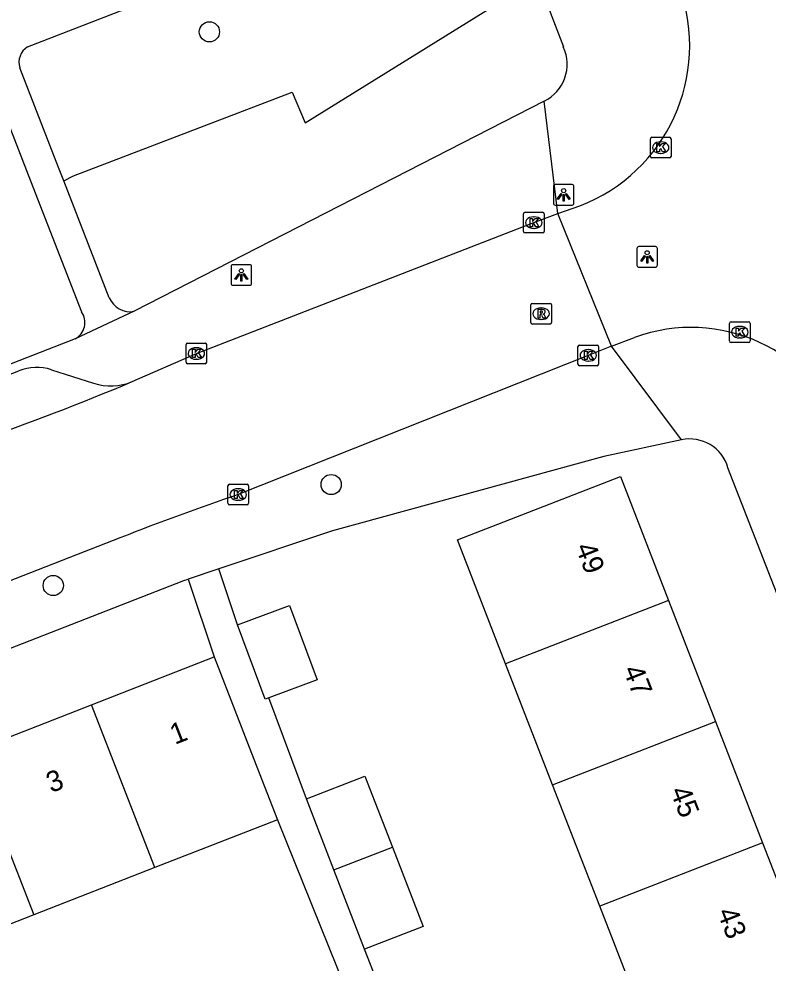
# Model space of a CAD drawing. Extents: x 159689 to 160786, y 387323 to 388339.
# Drawn here: x 160185.07 to 160221.36, y 387694.59 to 387740.35 of the extents above; entities that cross this region are included whole.
import ezdxf

# ---------------------------------------------------------------- set-up
doc = ezdxf.new("R2010")
doc.units = 0
for name, color, linetype in [('IMGEO_Boom', 7, 'Continuous'), ('IMGEO_Groenvoorziening', 7, 'Continuous'), ('IMGEO_Kolk', 7, 'Continuous'), ('IMGEO_Lichtpunt', 7, 'Continuous'), ('IMGEO_Pand', 7, 'Continuous'), ('IMGEO_Pand_nummerreeks', 7, 'Continuous'), ('IMGEO_Rijbaan_lokaal_gesloten', 7, 'Continuous'), ('IMGEO_Rijbaan_lokaal_open', 7, 'Continuous'), ('IMGEO_Rioolput', 7, 'Continuous'), ('IMGEO_Voetpad_open', 7, 'Continuous')]:
    doc.layers.add(name, color=color, linetype=linetype)

msp = doc.modelspace()

# ---------------------------------------------------------------- linework, layer by layer
at = {"layer": 'IMGEO_Boom'}
for centre in [(160194.295, 387739.718), (160200.196, 387717.781), (160186.733, 387712.89)]:
    msp.add_circle(centre, 0.489, dxfattribs=at)
at = {"layer": 'IMGEO_Groenvoorziening'}
msp.add_lwpolyline([(160187.24, 387732.505), (160187.714, 387732.742), (160198.307, 387736.801), (160198.939, 387735.303), (160208.031, 387740.94), (160210.196, 387742.282)], dxfattribs=at)
at = {"layer": 'IMGEO_Kolk'}
for p, q in [((160215.658, 387733.681), (160215.658, 387734.533)), ((160215.733, 387734.607), (160216.585, 387734.607)), ((160216.146, 387734.387), (160216.171, 387734.387)), ((160216.659, 387734.533), (160216.659, 387733.681)), ((160216.585, 387733.607), (160215.733, 387733.607)), ((160216.169, 387733.827), (160216.144, 387733.827)), ((160209.511, 387730.049), (160209.511, 387730.901)), ((160209.586, 387730.975), (160210.438, 387730.975)), ((160209.999, 387730.755), (160210.024, 387730.755)), ((160210.512, 387730.901), (160210.512, 387730.049)), ((160210.438, 387729.975), (160209.586, 387729.975)), ((160210.022, 387730.195), (160209.997, 387730.195)), ((160219.491, 387724.741), (160219.491, 387725.593)), ((160219.566, 387725.667), (160220.418, 387725.667)), ((160219.979, 387725.447), (160220.004, 387725.447)), ((160220.492, 387725.593), (160220.492, 387724.741)), ((160220.002, 387724.887), (160219.977, 387724.887)), ((160193.162, 387723.708), (160193.162, 387724.56)), ((160193.237, 387724.634), (160194.089, 387724.634)), ((160193.65, 387724.414), (160193.675, 387724.414)), ((160194.163, 387724.56), (160194.163, 387723.708)), ((160212.151, 387723.616), (160212.151, 387724.468)), ((160212.226, 387724.542), (160213.078, 387724.542)), ((160212.639, 387724.322), (160212.664, 387724.322)), ((160213.152, 387724.468), (160213.152, 387723.616)), ((160220.418, 387724.667), (160219.566, 387724.667)), ((160193.673, 387723.854), (160193.648, 387723.854)), ((160194.089, 387723.634), (160193.237, 387723.634)), ((160213.078, 387723.542), (160212.226, 387723.542)), ((160212.662, 387723.762), (160212.637, 387723.762)), ((160195.193, 387716.872), (160195.193, 387717.724)), ((160195.268, 387717.798), (160196.12, 387717.798)), ((160195.681, 387717.578), (160195.706, 387717.578)), ((160196.194, 387717.724), (160196.194, 387716.872)), ((160195.704, 387717.018), (160195.679, 387717.018)), ((160196.12, 387716.798), (160195.268, 387716.798))]:
    msp.add_line(p, q, dxfattribs=at)
for points in [[(160215.658, 387733.681), (160215.658, 387734.533)], [(160215.733, 387734.607), (160216.585, 387734.607)], [(160216.659, 387734.533), (160216.659, 387733.681)], [(160215.979, 387734.307), (160216.102, 387734.307), (160216.102, 387734.156), (160216.232, 387734.307), (160216.396, 387734.307), (160216.25, 387734.156), (160216.403, 387733.907), (160216.251, 387733.907), (160216.166, 387734.071), (160216.102, 387734.004), (160216.102, 387733.907), (160215.979, 387733.907), (160215.979, 387734.307)], [(160216.585, 387733.607), (160215.733, 387733.607)], [(160209.511, 387730.049), (160209.511, 387730.901)], [(160209.586, 387730.975), (160210.438, 387730.975)], [(160210.512, 387730.901), (160210.512, 387730.049)], [(160209.832, 387730.675), (160209.955, 387730.675), (160209.955, 387730.524), (160210.085, 387730.675), (160210.249, 387730.675), (160210.103, 387730.524), (160210.256, 387730.275), (160210.104, 387730.275), (160210.019, 387730.439), (160209.955, 387730.372), (160209.955, 387730.275), (160209.832, 387730.275), (160209.832, 387730.675)], [(160210.438, 387729.975), (160209.586, 387729.975)], [(160219.491, 387724.741), (160219.491, 387725.593)], [(160219.566, 387725.667), (160220.418, 387725.667)], [(160219.812, 387725.367), (160219.935, 387725.367), (160219.935, 387725.216), (160220.065, 387725.367), (160220.229, 387725.367), (160220.083, 387725.216), (160220.236, 387724.967), (160220.084, 387724.967), (160219.999, 387725.131), (160219.935, 387725.064), (160219.935, 387724.967), (160219.812, 387724.967), (160219.812, 387725.367)], [(160220.492, 387725.593), (160220.492, 387724.741)], [(160193.162, 387723.708), (160193.162, 387724.56)], [(160193.237, 387724.634), (160194.089, 387724.634)], [(160193.483, 387724.334), (160193.606, 387724.334), (160193.606, 387724.183), (160193.736, 387724.334), (160193.9, 387724.334), (160193.754, 387724.183), (160193.907, 387723.934), (160193.755, 387723.934), (160193.67, 387724.098), (160193.606, 387724.031), (160193.606, 387723.934), (160193.483, 387723.934), (160193.483, 387724.334)], [(160194.163, 387724.56), (160194.163, 387723.708)], [(160212.151, 387723.616), (160212.151, 387724.468)], [(160212.226, 387724.542), (160213.078, 387724.542)], [(160213.152, 387724.468), (160213.152, 387723.616)], [(160220.418, 387724.667), (160219.566, 387724.667)], [(160212.472, 387724.242), (160212.595, 387724.242), (160212.595, 387724.091), (160212.725, 387724.242), (160212.889, 387724.242), (160212.743, 387724.091), (160212.896, 387723.842), (160212.744, 387723.842), (160212.659, 387724.006), (160212.595, 387723.939), (160212.595, 387723.842), (160212.472, 387723.842), (160212.472, 387724.242)], [(160194.089, 387723.634), (160193.237, 387723.634)], [(160213.078, 387723.542), (160212.226, 387723.542)], [(160195.193, 387716.872), (160195.193, 387717.724)], [(160195.268, 387717.798), (160196.12, 387717.798)], [(160195.514, 387717.498), (160195.637, 387717.498), (160195.637, 387717.347), (160195.767, 387717.498), (160195.931, 387717.498), (160195.785, 387717.347), (160195.938, 387717.098), (160195.786, 387717.098), (160195.701, 387717.262), (160195.637, 387717.195), (160195.637, 387717.098), (160195.514, 387717.098), (160195.514, 387717.498)], [(160196.194, 387717.724), (160196.194, 387716.872)], [(160196.12, 387716.798), (160195.268, 387716.798)]]:
    msp.add_lwpolyline(points, dxfattribs=at)
for centre, start, end in [((160215.735, 387734.531), 91.552, 178.448), ((160215.735, 387734.531), 91.552, 178.448), ((160216.583, 387734.531), 1.552, 88.448), ((160216.583, 387734.531), 1.552, 88.448), ((160215.735, 387733.683), 181.552, 268.448), ((160215.735, 387733.683), 181.552, 268.448), ((160216.583, 387733.683), 271.552, 358.448), ((160216.583, 387733.683), 271.552, 358.448), ((160209.588, 387730.899), 91.552, 178.448), ((160209.588, 387730.899), 91.552, 178.448), ((160210.436, 387730.899), 1.552, 88.448), ((160210.436, 387730.899), 1.552, 88.448), ((160209.588, 387730.051), 181.552, 268.448), ((160209.588, 387730.051), 181.552, 268.448), ((160210.436, 387730.051), 271.552, 358.448), ((160210.436, 387730.051), 271.552, 358.448), ((160219.568, 387725.591), 91.552, 178.448), ((160219.568, 387725.591), 91.552, 178.448), ((160220.416, 387725.591), 1.552, 88.448), ((160220.416, 387725.591), 1.552, 88.448), ((160193.239, 387724.558), 91.552, 178.448), ((160193.239, 387724.558), 91.552, 178.448), ((160194.087, 387724.558), 1.552, 88.448), ((160194.087, 387724.558), 1.552, 88.448), ((160212.228, 387724.466), 91.552, 178.448), ((160212.228, 387724.466), 91.552, 178.448), ((160213.076, 387724.466), 1.552, 88.448), ((160213.076, 387724.466), 1.552, 88.448), ((160219.568, 387724.743), 181.552, 268.448), ((160219.568, 387724.743), 181.552, 268.448), ((160220.416, 387724.743), 271.552, 358.448), ((160220.416, 387724.743), 271.552, 358.448), ((160193.239, 387723.71), 181.552, 268.448), ((160193.239, 387723.71), 181.552, 268.448), ((160194.087, 387723.71), 271.552, 358.448), ((160194.087, 387723.71), 271.552, 358.448), ((160212.228, 387723.618), 181.552, 268.448), ((160212.228, 387723.618), 181.552, 268.448), ((160213.076, 387723.618), 271.552, 358.448), ((160213.076, 387723.618), 271.552, 358.448), ((160195.27, 387717.722), 91.552, 178.448), ((160195.27, 387717.722), 91.552, 178.448), ((160196.118, 387717.722), 1.552, 88.448), ((160196.118, 387717.722), 1.552, 88.448), ((160195.27, 387716.874), 181.552, 268.448), ((160195.27, 387716.874), 181.552, 268.448), ((160196.118, 387716.874), 271.552, 358.448), ((160196.118, 387716.874), 271.552, 358.448)]:
    msp.add_arc(centre, 0.0765, start, end, dxfattribs=at)
for centre, major_axis, ratio, start_param, end_param in [((160216.145, 387734.107), (-0.387, 0.002), 0.722429, 4.712389, 7.853982), ((160216.17, 387734.107), (-0.39, 0.002), 0.717154, 1.570796, 4.712389), ((160209.998, 387730.475), (-0.387, 0.002), 0.722429, 4.712389, 7.853982), ((160210.023, 387730.475), (-0.39, 0.002), 0.717154, 1.570796, 4.712389), ((160219.978, 387725.167), (-0.387, 0.002), 0.722429, 4.712389, 7.853982), ((160220.003, 387725.167), (-0.39, 0.002), 0.717154, 1.570796, 4.712389), ((160193.649, 387724.134), (-0.387, 0.002), 0.722429, 4.712389, 7.853982), ((160193.674, 387724.134), (-0.39, 0.002), 0.717154, 1.570796, 4.712389), ((160212.638, 387724.042), (-0.387, 0.002), 0.722429, 4.712389, 7.853982), ((160212.663, 387724.042), (-0.39, 0.002), 0.717154, 1.570796, 4.712389), ((160195.68, 387717.298), (-0.387, 0.002), 0.722429, 4.712389, 7.853982), ((160195.705, 387717.298), (-0.39, 0.002), 0.717154, 1.570796, 4.712389)]:
    msp.add_ellipse(centre, major_axis=major_axis, ratio=ratio, start_param=start_param, end_param=end_param, dxfattribs=at)
at = {"layer": 'IMGEO_Lichtpunt'}
for p, q in [((160210.96, 387732.224), (160210.96, 387731.417)), ((160210.96, 387732.224), (160210.96, 387731.417)), ((160211.862, 387732.319), (160211.054, 387732.319)), ((160211.862, 387732.319), (160211.054, 387732.319)), ((160211.956, 387731.417), (160211.956, 387732.224)), ((160211.956, 387731.417), (160211.956, 387732.224)), ((160211.054, 387731.323), (160211.862, 387731.323)), ((160211.054, 387731.323), (160211.862, 387731.323)), ((160215.005, 387729.216), (160215.005, 387728.409)), ((160215.005, 387729.216), (160215.005, 387728.409)), ((160215.907, 387729.311), (160215.099, 387729.311)), ((160215.907, 387729.311), (160215.099, 387729.311)), ((160216.001, 387728.409), (160216.001, 387729.216)), ((160216.001, 387728.409), (160216.001, 387729.216)), ((160196.245, 387728.435), (160195.437, 387728.435)), ((160196.245, 387728.435), (160195.437, 387728.435)), ((160195.343, 387728.34), (160195.343, 387727.533)), ((160195.343, 387728.34), (160195.343, 387727.533)), ((160196.339, 387727.533), (160196.339, 387728.34)), ((160196.339, 387727.533), (160196.339, 387728.34)), ((160215.099, 387728.315), (160215.907, 387728.315)), ((160215.099, 387728.315), (160215.907, 387728.315)), ((160195.437, 387727.439), (160196.245, 387727.439)), ((160195.437, 387727.439), (160196.245, 387727.439))]:
    msp.add_line(p, q, dxfattribs=at)
for points in [[(160211.334, 387731.888), (160211.373, 387731.86), (160211.185, 387731.598), (160211.147, 387731.625), (160211.334, 387731.888)], [(160211.436, 387731.84), (160211.483, 387731.84), (160211.483, 387731.518), (160211.436, 387731.518), (160211.436, 387731.84)], [(160211.546, 387731.86), (160211.584, 387731.887), (160211.771, 387731.625), (160211.732, 387731.597), (160211.546, 387731.86)], [(160215.379, 387728.88), (160215.418, 387728.852), (160215.23, 387728.59), (160215.192, 387728.617), (160215.379, 387728.88)], [(160215.481, 387728.832), (160215.528, 387728.832), (160215.528, 387728.51), (160215.481, 387728.51), (160215.481, 387728.832)], [(160215.591, 387728.852), (160215.629, 387728.879), (160215.816, 387728.617), (160215.777, 387728.589), (160215.591, 387728.852)], [(160195.717, 387728.004), (160195.756, 387727.976), (160195.568, 387727.714), (160195.53, 387727.741), (160195.717, 387728.004)], [(160195.929, 387727.976), (160195.967, 387728.003), (160196.154, 387727.741), (160196.115, 387727.713), (160195.929, 387727.976)], [(160195.819, 387727.956), (160195.866, 387727.956), (160195.866, 387727.634), (160195.819, 387727.634), (160195.819, 387727.956)]]:
    msp.add_lwpolyline(points, dxfattribs=at)
for centre in [(160211.459, 387732.022), (160215.504, 387729.014), (160195.842, 387728.138)]:
    msp.add_circle(centre, 0.0994, dxfattribs=at)
for centre, start, end in [((160211.054, 387732.224), 90, 180), ((160211.054, 387732.224), 90, 180), ((160211.862, 387732.224), 0, 90), ((160211.862, 387732.224), 0, 90), ((160211.054, 387731.417), 180, 270), ((160211.054, 387731.417), 180, 270), ((160211.862, 387731.417), 270, 0), ((160211.862, 387731.417), 270, 360), ((160215.099, 387729.216), 90, 180), ((160215.099, 387729.216), 90, 180), ((160215.907, 387729.216), 0, 90), ((160215.907, 387729.216), 0, 90), ((160195.437, 387728.34), 90, 180), ((160195.437, 387728.34), 90, 180), ((160196.245, 387728.34), 0, 90), ((160196.245, 387728.34), 0, 90), ((160215.099, 387728.409), 180, 270), ((160215.099, 387728.409), 180, 270), ((160215.907, 387728.409), 270, 0), ((160215.907, 387728.409), 270, 360), ((160195.437, 387727.533), 180, 270), ((160195.437, 387727.533), 180, 270), ((160196.245, 387727.533), 270, 0), ((160196.245, 387727.533), 270, 360)]:
    msp.add_arc(centre, 0.0946, start, end, dxfattribs=at)
at = {"layer": 'IMGEO_Pand'}
for points in [[(160208.641, 387709.102), (160206.312, 387715.099), (160214.204, 387718.165), (160216.534, 387712.167)], [(160216.534, 387712.167), (160208.641, 387709.102)], [(160216.534, 387712.167), (160218.815, 387706.295)], [(160195.659, 387710.979), (160198.176, 387711.917), (160199.514, 387708.327), (160197.168, 387707.453)], [(160197.168, 387707.453), (160196.996, 387707.389), (160195.659, 387710.979)], [(160188.578, 387707.108), (160194.521, 387709.43)], [(160194.521, 387709.43), (160196.34, 387704.773), (160197.602, 387701.542)], [(160210.922, 387703.23), (160208.641, 387709.102)], [(160182.71, 387704.816), (160188.578, 387707.108)], [(160191.659, 387699.221), (160188.578, 387707.108)], [(160210.922, 387703.23), (160218.815, 387706.295)], [(160218.815, 387706.295), (160221.096, 387700.422)], [(160182.71, 387704.816), (160185.791, 387696.929)], [(160198.995, 387702.55), (160201.833, 387703.647), (160203.159, 387700.215)], [(160213.203, 387697.357), (160210.922, 387703.23)], [(160200.323, 387699.114), (160198.995, 387702.55)], [(160197.602, 387701.542), (160191.659, 387699.221)], [(160200.323, 387699.114), (160203.159, 387700.215)], [(160203.159, 387700.215), (160204.648, 387696.36), (160201.81, 387695.264)], [(160221.096, 387700.422), (160213.203, 387697.357)], [(160221.096, 387700.422), (160223.377, 387694.549)], [(160191.659, 387699.221), (160185.791, 387696.929)], [(160201.81, 387695.264), (160200.323, 387699.114)], [(160215.484, 387691.485), (160213.203, 387697.357)], [(160185.791, 387696.929), (160179.923, 387694.636)]]:
    msp.add_lwpolyline(points, dxfattribs=at)
at = {"layer": 'IMGEO_Rijbaan_lokaal_gesloten'}
for points in [[(160211.179, 387730.91), (160212.241, 387731.291)], [(160213.774, 387724.486), (160211.179, 387730.91)], [(160213.774, 387724.486), (160214.883, 387724.908)]]:
    msp.add_lwpolyline(points, dxfattribs=at)
for centre, radius, start, end in [((160209.273, 387739.033), 8.291, 290.9715, 19.9774), ((160217.624, 387717.4), 7.993, 20.7998, 110.0547)]:
    msp.add_arc(centre, radius, start, end, dxfattribs=at)
at = {"layer": 'IMGEO_Rijbaan_lokaal_open'}
for points in [[(160190.56, 387722.769), (160193.663, 387724.134), (160210.012, 387730.475), (160211.179, 387730.91)], [(160213.774, 387724.486), (160212.652, 387724.042), (160195.693, 387717.297)], [(160190, 387715.208), (160155.133, 387701.581), (160119.003, 387687.495), (160085.401, 387674.408), (160057.185, 387663.329)]]:
    msp.add_lwpolyline(points, dxfattribs=at)
for centre, radius, start, end in [((160142.899, 387835.721), 122.596, 289.08558, 292.87789), ((160234.536, 387602.64), 121.058, 108.71499, 111.58541)]:
    msp.add_arc(centre, radius, start, end, dxfattribs=at)
at = {"layer": 'IMGEO_Rioolput'}
for p, q in [((160209.866, 387725.634), (160209.866, 387726.486)), ((160209.941, 387726.56), (160210.793, 387726.56)), ((160210.354, 387726.34), (160210.379, 387726.34)), ((160210.867, 387726.486), (160210.867, 387725.634)), ((160210.377, 387725.78), (160210.352, 387725.78)), ((160210.793, 387725.56), (160209.941, 387725.56))]:
    msp.add_line(p, q, dxfattribs=at)
for points in [[(160209.866, 387725.634), (160209.866, 387726.486)], [(160209.941, 387726.56), (160210.793, 387726.56)], [(160210.455, 387726.258), (160210.203, 387726.26), (160210.203, 387725.86)], [(160210.381, 387726.179), (160210.327, 387726.179), (160210.327, 387726.098)], [(160210.867, 387726.486), (160210.867, 387725.634)], [(160210.203, 387725.86), (160210.327, 387725.86), (160210.327, 387726.022), (160210.338, 387726.022)], [(160210.327, 387726.098), (160210.379, 387726.098)], [(160210.385, 387725.993), (160210.456, 387725.86), (160210.596, 387725.86), (160210.531, 387725.986)], [(160210.793, 387725.56), (160209.941, 387725.56)]]:
    msp.add_lwpolyline(points, dxfattribs=at)
for centre, radius, start, end in [((160209.943, 387726.484), 0.0765, 91.552, 178.448), ((160209.943, 387726.484), 0.0765, 91.552, 178.448), ((160210.387, 387726.083), 0.0964, 77.0061, 93.1865), ((160210.401, 387726.14), 0.0378, 276.6634, 79.6772), ((160210.454, 387726.148), 0.109, 350.3612, 89.416), ((160210.791, 387726.484), 0.0765, 1.552, 88.448), ((160210.791, 387726.484), 0.0765, 1.552, 88.448), ((160210.337, 387725.969), 0.0533, 26.0293, 88.6989), ((160210.363, 387726.287), 0.19, 274.7715, 282.9687), ((160210.452, 387726.148), 0.112, 277.5842, 350.9817), ((160210.436, 387725.933), 0.108, 29.5134, 73.7905), ((160209.943, 387725.636), 0.0765, 181.552, 268.448), ((160209.943, 387725.636), 0.0765, 181.552, 268.448), ((160210.791, 387725.636), 0.0765, 271.552, 358.448), ((160210.791, 387725.636), 0.0765, 271.552, 358.448)]:
    msp.add_arc(centre, radius, start, end, dxfattribs=at)
for centre, major_axis, ratio, start_param, end_param in [((160210.353, 387726.06), (-0.387, 0.002), 0.722429, 4.712389, 7.853982), ((160210.378, 387726.06), (-0.39, 0.002), 0.717154, 1.570796, 4.712389)]:
    msp.add_ellipse(centre, major_axis=major_axis, ratio=ratio, start_param=start_param, end_param=end_param, dxfattribs=at)
at = {"layer": 'IMGEO_Voetpad_open'}
for points in [[(160185.483, 387738.985), (160195.708, 387742.96), (160198.714, 387744.129), (160205.834, 387747.014)], [(160210.196, 387742.282), (160211.442, 387738.984)], [(160187.24, 387732.505), (160186.993, 387733.138), (160185.108, 387737.978)], [(160183.749, 387737.288), (160185.621, 387732.5), (160188.102, 387726.158)], [(160210.511, 387736.364), (160190.649, 387726.18)], [(160211.179, 387730.91), (160210.511, 387736.364)], [(160189.447, 387726.837), (160187.24, 387732.505)], [(160190.649, 387726.18), (160187.794, 387724.84)], [(160187.794, 387724.84), (160164.624, 387715.802)], [(160217.16, 387719.947), (160213.774, 387724.486)], [(160057.664, 387673.563), (160058.019, 387673.764), (160088.425, 387685.547), (160132.762, 387702.9), (160185.066, 387723.299)], [(160186.64, 387723.346), (160188.683, 387722.688)], [(160217.16, 387719.947), (160213.396, 387719.139), (160200.266, 387715.532), (160194.754, 387713.699)], [(160237.706, 387671.712), (160219.418, 387718.599)], [(160194.754, 387713.699), (160193.266, 387713.204)], [(160195.659, 387710.979), (160194.754, 387713.699)], [(160140.108, 387692.465), (160193.051, 387713.133), (160193.266, 387713.204)], [(160193.266, 387713.204), (160194.521, 387709.43)], [(160198.995, 387702.55), (160197.168, 387707.453)], [(160197.602, 387701.542), (160200.884, 387693.355)], [(160203.557, 387690.804), (160201.81, 387695.264)]]:
    msp.add_lwpolyline(points, dxfattribs=at)
for centre, radius, start, end in [((160185.944, 387738.24), 0.876, 121.7344, 197.4156), ((160209.649, 387738.146), 1.979, 295.8204, 25.0549), ((160190.438, 387727.221), 1.063, 201.2109, 281.468), ((160187.347, 387725.639), 0.916, 299.1964, 34.4971), ((160185.919, 387721.105), 2.354, 72.1726, 111.2482), ((160189.512, 387725.258), 2.7, 252.1128, 292.8293), ((160217.562, 387718.055), 1.934, 16.333, 101.9936)]:
    msp.add_arc(centre, radius, start, end, dxfattribs=at)

# ---------------------------------------------------------------- texts
at = {"layer": 'IMGEO_Pand_nummerreeks'}
for s, rotation, p in [('49', 291.2293, (160212.012, 387714.749)), ('47', 291.2288, (160214.319, 387708.811)), ('1', 21.3373, (160192.622, 387705.166)), ('3', 21.3373, (160186.631, 387702.827)), ('45', 291.2255, (160216.6, 387702.939)), ('43', 291.2255, (160218.881, 387697.066))]:
    msp.add_text(s, height=1, rotation=rotation, dxfattribs=at).set_placement(p)

doc.saveas('drawing.dxf')
